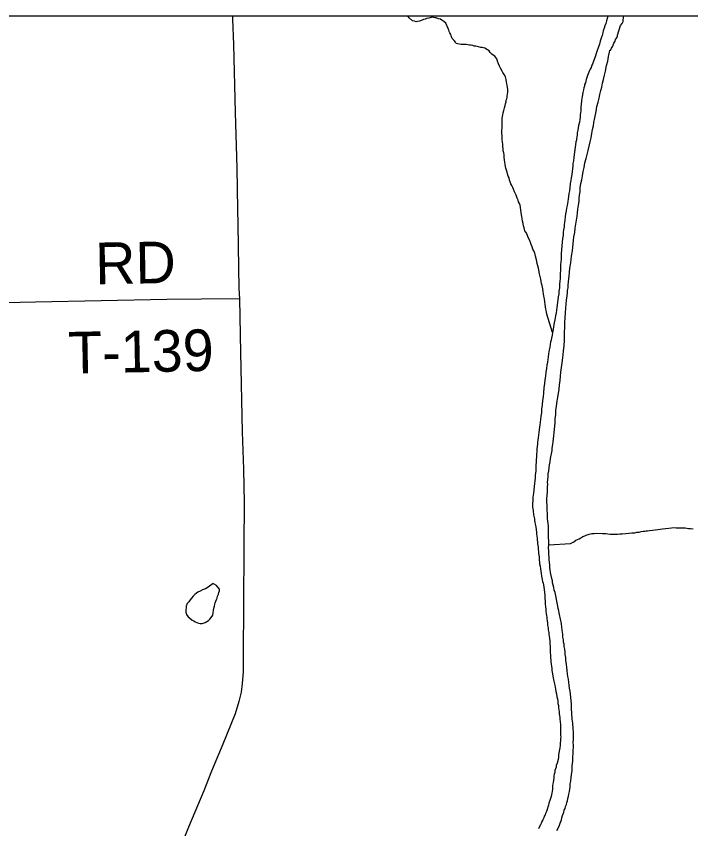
# Model space of a CAD drawing. Extents: x 0 to 34, y 0 to 22.
# Drawn here: x 5.67 to 6.59, y 20.03 to 21.138 of the extents above; entities that cross this region are included whole.
import ezdxf

# ---------------------------------------------------------------- set-up
doc = ezdxf.new("R2010")
doc.units = 0
for name, color, linetype in [('GM_X_County', 7, 'Continuous'), ('GM_X_County_Road', 7, 'Continuous'), ('GM_X_Major_River', 7, 'Continuous'), ('GM_X_Minor_Lake', 7, 'Continuous'), ('GM_X_Minor_River', 7, 'Continuous'), ('GM_X_Township', 7, 'Continuous'), ('GM_X_Township_Road', 7, 'Continuous'), ('GM_X_Township_Road_Text', 7, 'Continuous')]:
    doc.layers.add(name, color=color, linetype=linetype)

msp = doc.modelspace()

# ---------------------------------------------------------------- linework, layer by layer
at = {"layer": 'GM_X_County'}
msp.add_lwpolyline([(9.1622, 14.342), (9.1622, 21.1385), (2.3622, 21.1385), (2.3622, 14.3385), (9.0003, 14.3385)], dxfattribs=at)
at = {"layer": 'GM_X_County_Road'}
msp.add_lwpolyline([(5.965, 21.1385), (5.965, 21.1347), (5.9663, 21.1001), (5.9684, 21.0071), (5.9708, 20.9314), (5.9719, 20.8756), (5.9723, 20.8541), (5.9737, 20.7672), (5.9744, 20.7533), (5.9759, 20.6798), (5.9783, 20.5719), (5.9798, 20.521), (5.9807, 20.4747), (5.9805, 20.4173), (5.98, 20.3324), (5.9795, 20.2706), (5.9795, 20.2444), (5.9783, 20.2284), (5.9766, 20.2165), (5.9737, 20.2042), (5.9686, 20.1872), (5.9517, 20.146), (5.9364, 20.1089), (5.9257, 20.0822), (5.9051, 20.0328), (5.8816, 19.9746)], dxfattribs=at)
at = {"layer": 'GM_X_Major_River'}
for points in [[(6.4766, 21.1385), (6.4758, 21.1355), (6.4747, 21.1321), (6.4737, 21.1287), (6.4726, 21.1252), (6.4715, 21.1222), (6.4705, 21.1187), (6.4698, 21.1157), (6.4687, 21.1122), (6.4676, 21.1084), (6.4662, 21.1046), (6.4652, 21.1004), (6.4634, 21.0954), (6.4623, 21.0916), (6.4609, 21.0877), (6.4598, 21.0843), (6.4566, 21.0759), (6.4559, 21.0732), (6.4544, 21.0709), (6.4537, 21.0686), (6.4526, 21.0663), (6.4515, 21.0643), (6.4508, 21.0621), (6.45, 21.0601), (6.449, 21.0578), (6.4472, 21.0521), (6.4465, 21.0498), (6.4461, 21.0479), (6.445, 21.0452), (6.4447, 21.0433)], [(6.4796, 21.0923), (6.4809, 21.0922), (6.4809, 21.0928), (6.4815, 21.0948), (6.4834, 21.0979), (6.4847, 21.1018), (6.4866, 21.1043), (6.4873, 21.1069), (6.4886, 21.1088), (6.4892, 21.1101), (6.4898, 21.1107), (6.4898, 21.1114), (6.4898, 21.1126), (6.4937, 21.1261), (6.4962, 21.1286), (6.4969, 21.1305), (6.4975, 21.1312), (6.4975, 21.1331), (6.4982, 21.1369), (6.4985, 21.1385)], [(6.4351, 20.8702), (6.4357, 20.8752), (6.4368, 20.8809), (6.4374, 20.8858), (6.4377, 20.8904), (6.438, 20.8946), (6.4387, 20.8992), (6.4389, 20.9045), (6.4399, 20.9102), (6.441, 20.9156), (6.442, 20.9209), (6.443, 20.9266), (6.4444, 20.9324), (6.4454, 20.9388), (6.4472, 20.9446), (6.4486, 20.9499), (6.45, 20.9553), (6.451, 20.9614), (6.4524, 20.9671), (6.4538, 20.9728), (6.4548, 20.9786), (6.4559, 20.9839), (6.4569, 20.9889), (6.4575, 20.9938), (6.4589, 20.9999), (6.4607, 21.0087), (6.4617, 21.0152), (6.4634, 21.0213), (6.4648, 21.0266), (6.4659, 21.032), (6.4669, 21.0373), (6.4683, 21.0419), (6.4693, 21.0473), (6.4708, 21.0522), (6.4722, 21.058), (6.4736, 21.0637), (6.4749, 21.0713), (6.4767, 21.0774), (6.4777, 21.0835), (6.4791, 21.0893), (6.4796, 21.0923)], [(6.4447, 21.0433), (6.444, 21.041), (6.4433, 21.0383), (6.4429, 21.0364), (6.4426, 21.0345), (6.4419, 21.0315), (6.4416, 21.0292), (6.4413, 21.0265), (6.4409, 21.0235), (6.4406, 21.0216), (6.4403, 21.0197), (6.4403, 21.0178), (6.44, 21.0155), (6.44, 21.0136), (6.4397, 21.0117), (6.4397, 21.0094), (6.4394, 21.0067), (6.4391, 21.004), (6.4388, 21.001), (6.4384, 20.9976), (6.4378, 20.9941), (6.4367, 20.9896), (6.4364, 20.9865), (6.4357, 20.9831), (6.435, 20.9796), (6.4347, 20.9766), (6.4344, 20.9735), (6.4341, 20.9716), (6.4337, 20.9694), (6.433, 20.9671), (6.4327, 20.9633), (6.4307, 20.9499), (6.4301, 20.9457), (6.4298, 20.9415), (6.4291, 20.9377), (6.4288, 20.9343), (6.4285, 20.9305), (6.4278, 20.9267), (6.4275, 20.9225), (6.4268, 20.9183), (6.4262, 20.9145), (6.4255, 20.9103), (6.4248, 20.9046), (6.4242, 20.9004), (6.4235, 20.8966), (6.4232, 20.8928), (6.4225, 20.8893), (6.4222, 20.8859), (6.4215, 20.8832), (6.4212, 20.8802), (6.4205, 20.8767), (6.4198, 20.8729), (6.4191, 20.8691), (6.4185, 20.8649), (6.4178, 20.8603), (6.4175, 20.8573), (6.4172, 20.8543), (6.4169, 20.8512), (6.4162, 20.8474), (6.4159, 20.8436), (6.4156, 20.8394), (6.4149, 20.8352), (6.4143, 20.8303), (6.414, 20.8253), (6.4133, 20.8204), (6.4131, 20.8146), (6.4128, 20.8108), (6.4129, 20.8074), (6.4126, 20.8036), (6.4123, 20.7998), (6.4123, 20.796), (6.412, 20.7918), (6.4117, 20.788), (6.4118, 20.7846), (6.4115, 20.7808), (6.4112, 20.7774), (6.4109, 20.7732), (6.4107, 20.7679), (6.41, 20.7637), (6.4097, 20.7599), (6.409, 20.7557), (6.4077, 20.7446), (6.407, 20.7412), (6.4067, 20.7378), (6.4061, 20.7339), (6.4054, 20.7298), (6.4044, 20.7244), (6.4037, 20.7202), (6.4026, 20.7156), (6.402, 20.7114), (6.4013, 20.7072), (6.4006, 20.7034), (6.3999, 20.6996), (6.3992, 20.6969), (6.3985, 20.6943), (6.3982, 20.6908), (6.3975, 20.6874), (6.3965, 20.6836), (6.3958, 20.6783), (6.3952, 20.6741), (6.3949, 20.6703)], [(6.401, 20.3687), (6.4001, 20.3717), (6.3993, 20.3759), (6.3984, 20.3801), (6.398, 20.3835), (6.3975, 20.3869), (6.3974, 20.3903), (6.397, 20.3937), (6.3965, 20.3975), (6.3965, 20.4009), (6.3964, 20.4051), (6.3963, 20.4093), (6.3958, 20.4134), (6.3961, 20.4176), (6.396, 20.4229), (6.3959, 20.4271), (6.3958, 20.4313), (6.3957, 20.4355), (6.3956, 20.4393), (6.3956, 20.4431), (6.3951, 20.4465), (6.395, 20.4499), (6.3946, 20.4537), (6.3945, 20.4571), (6.3944, 20.4605), (6.394, 20.4647), (6.3939, 20.4685), (6.3938, 20.4719), (6.3937, 20.4757), (6.3936, 20.4803), (6.3939, 20.4852), (6.3942, 20.4894), (6.3945, 20.4932), (6.3944, 20.4966), (6.3947, 20.4997), (6.3946, 20.5031), (6.395, 20.5061), (6.3952, 20.5107), (6.3955, 20.5145), (6.3962, 20.5187), (6.3965, 20.5225), (6.3972, 20.5267), (6.3979, 20.5309), (6.3985, 20.5355), (6.4006, 20.5461), (6.4009, 20.5496), (6.4015, 20.5545), (6.4022, 20.5583), (6.4025, 20.5621), (6.4032, 20.5663), (6.4035, 20.5709), (6.4041, 20.5751), (6.4044, 20.5797), (6.4047, 20.5842), (6.405, 20.5895), (6.4056, 20.5953), (6.4059, 20.601), (6.4065, 20.6067), (6.4075, 20.6135), (6.4085, 20.6189), (6.4092, 20.6242), (6.4102, 20.6299), (6.4108, 20.636), (6.4115, 20.6417), (6.4121, 20.6475), (6.4127, 20.6532), (6.4137, 20.6593), (6.4144, 20.6657), (6.4154, 20.6726), (6.4163, 20.6817), (6.4173, 20.6894), (6.4175, 20.6962), (6.4174, 20.7019), (6.4177, 20.7076), (6.4179, 20.7141), (6.4181, 20.7209), (6.4184, 20.7274), (6.419, 20.7338), (6.4196, 20.7403), (6.4199, 20.746), (6.4205, 20.7514), (6.4212, 20.7571), (6.4215, 20.7613), (6.4218, 20.7647), (6.4224, 20.7681), (6.4227, 20.7719), (6.423, 20.7761), (6.4237, 20.7803), (6.424, 20.7845), (6.4243, 20.7891), (6.4249, 20.7951), (6.4263, 20.802), (6.4272, 20.8115), (6.4286, 20.8188), (6.4305, 20.8378), (6.4315, 20.8435), (6.4321, 20.8496), (6.4331, 20.855), (6.4338, 20.8603), (6.4348, 20.8657), (6.4351, 20.8702)], [(6.3949, 20.6703), (6.3942, 20.6668), (6.3935, 20.6626), (6.3928, 20.6581), (6.3922, 20.6531), (6.3915, 20.6478), (6.3909, 20.6428), (6.3902, 20.6375), (6.3896, 20.6318), (6.389, 20.6249), (6.3883, 20.6196), (6.3877, 20.6143), (6.3871, 20.6085), (6.3864, 20.6028), (6.3862, 20.5975), (6.3855, 20.5929), (6.3848, 20.5887), (6.3845, 20.5849), (6.3838, 20.5815), (6.3835, 20.5781), (6.3828, 20.575), (6.3825, 20.5708), (6.3819, 20.5674), (6.3816, 20.5636), (6.3813, 20.5602), (6.3809, 20.5575), (6.3806, 20.5548), (6.3803, 20.5518), (6.38, 20.5487), (6.3797, 20.5449), (6.3794, 20.5415), (6.3789, 20.5297), (6.3785, 20.5267), (6.3786, 20.5236), (6.3783, 20.521), (6.3783, 20.5183), (6.378, 20.5156), (6.3777, 20.5122), (6.3774, 20.5088), (6.3771, 20.505), (6.3768, 20.5012), (6.3761, 20.4974), (6.3759, 20.4924), (6.3752, 20.4882), (6.3749, 20.4852), (6.3745, 20.4825), (6.3742, 20.4791), (6.3743, 20.4772), (6.374, 20.4749), (6.374, 20.4722), (6.3741, 20.4688), (6.3745, 20.4665), (6.3749, 20.4647), (6.375, 20.4624), (6.3754, 20.4605), (6.3754, 20.4586), (6.3759, 20.4567), (6.3763, 20.4548), (6.3767, 20.4529), (6.3767, 20.451), (6.3772, 20.4484), (6.3776, 20.4457), (6.3785, 20.4423), (6.3789, 20.4381), (6.3794, 20.4347), (6.3794, 20.4321), (6.3799, 20.4294), (6.3803, 20.4268), (6.3804, 20.4241), (6.3808, 20.4219), (6.3809, 20.4188), (6.3813, 20.4165), (6.3817, 20.4143), (6.3818, 20.4116), (6.3822, 20.4082), (6.3823, 20.4059), (6.3827, 20.4037), (6.3828, 20.4014), (6.3828, 20.3995), (6.3837, 20.3919), (6.3842, 20.3885), (6.385, 20.3851), (6.3855, 20.3817), (6.3859, 20.3787), (6.3864, 20.3749), (6.3868, 20.3726), (6.3872, 20.3703), (6.3877, 20.3677), (6.3885, 20.3654), (6.3889, 20.3631), (6.3893, 20.3601), (6.3898, 20.3567), (6.3903, 20.3525), (6.3907, 20.3487), (6.3908, 20.3453), (6.3913, 20.3404), (6.3914, 20.3366), (6.3918, 20.3332), (6.3919, 20.3298), (6.392, 20.3267), (6.3924, 20.3241)], [(6.4071, 20.028), (6.4093, 20.0323), (6.4108, 20.0353), (6.4115, 20.038), (6.4126, 20.0403), (6.4133, 20.0426), (6.414, 20.0453), (6.415, 20.0483), (6.4158, 20.0506), (6.4165, 20.0529), (6.4172, 20.0556), (6.4183, 20.0579), (6.419, 20.061), (6.4201, 20.0633), (6.4207, 20.0663), (6.4215, 20.0686), (6.4222, 20.0717), (6.4229, 20.0747), (6.4235, 20.0778), (6.4242, 20.0812), (6.4249, 20.0843), (6.4252, 20.0877), (6.4255, 20.0915), (6.4262, 20.0953), (6.4265, 20.1007), (6.4272, 20.1041), (6.4275, 20.1071), (6.4278, 20.1094), (6.4278, 20.1113), (6.4281, 20.114), (6.428, 20.1163), (6.4284, 20.1193), (6.4287, 20.1227), (6.429, 20.1258), (6.4289, 20.1288), (6.4292, 20.1326), (6.4295, 20.1353), (6.4295, 20.138), (6.4298, 20.141), (6.4297, 20.1444), (6.4296, 20.1482), (6.4299, 20.152), (6.4297, 20.1627), (6.4296, 20.1661), (6.4292, 20.1691), (6.4291, 20.1721), (6.4287, 20.1744), (6.4286, 20.1771), (6.4282, 20.1797), (6.4282, 20.182), (6.4277, 20.1854), (6.4276, 20.1892), (6.4272, 20.193), (6.4271, 20.1968), (6.427, 20.2006), (6.4265, 20.2048), (6.426, 20.2097), (6.4256, 20.2139), (6.4251, 20.218), (6.4246, 20.2222), (6.4238, 20.2264), (6.4233, 20.2301), (6.4229, 20.2343), (6.422, 20.2381), (6.4216, 20.2419), (6.4211, 20.2461), (6.4206, 20.2502), (6.4201, 20.2548), (6.4196, 20.2601), (6.4192, 20.2642), (6.4187, 20.268), (6.4183, 20.2714), (6.4178, 20.2752), (6.4173, 20.279), (6.4169, 20.2821), (6.4164, 20.2851), (6.416, 20.2881), (6.4155, 20.2915), (6.4155, 20.2957), (6.4146, 20.3014), (6.4141, 20.3056), (6.4133, 20.3093), (6.4128, 20.3127), (6.412, 20.3161), (6.4115, 20.3184), (6.4111, 20.3203), (6.4107, 20.3226), (6.4103, 20.3248), (6.4098, 20.3275), (6.409, 20.3309), (6.4085, 20.3339), (6.4077, 20.3385), (6.4056, 20.3483), (6.4047, 20.3525), (6.4035, 20.3559), (6.4031, 20.3596), (6.4022, 20.3627), (6.4014, 20.3657), (6.401, 20.3687)], [(6.3924, 20.3241), (6.3928, 20.321), (6.3933, 20.3188), (6.3937, 20.3165), (6.3941, 20.3139), (6.3942, 20.3108), (6.3946, 20.3082), (6.3951, 20.3044), (6.3955, 20.3017), (6.396, 20.2979), (6.3961, 20.2957), (6.3965, 20.293), (6.3969, 20.29), (6.3974, 20.2866), (6.3975, 20.2832), (6.3979, 20.279), (6.398, 20.2748), (6.3981, 20.2703), (6.3986, 20.2676), (6.3986, 20.2653), (6.3987, 20.263), (6.3991, 20.2608), (6.3991, 20.2581), (6.3996, 20.2551), (6.4, 20.2521), (6.4001, 20.249), (6.4002, 20.2464), (6.4006, 20.2441), (6.4023, 20.2361), (6.4027, 20.2339), (6.4031, 20.2316), (6.404, 20.2282), (6.4044, 20.2263), (6.4048, 20.2237), (6.4053, 20.2206), (6.4057, 20.2176), (6.4065, 20.2146), (6.407, 20.2104), (6.4078, 20.2074), (6.4083, 20.2044), (6.4087, 20.2013), (6.4092, 20.1983), (6.4092, 20.1953), (6.4097, 20.1926), (6.4101, 20.19), (6.4102, 20.1873), (6.4106, 20.1847), (6.411, 20.182), (6.4111, 20.1797), (6.4115, 20.1763), (6.412, 20.1725), (6.4121, 20.1702), (6.4121, 20.1683), (6.4121, 20.1665), (6.4122, 20.1642), (6.4122, 20.1615), (6.4123, 20.1596), (6.4123, 20.1577), (6.4124, 20.1558), (6.412, 20.1532), (6.4121, 20.1509), (6.4118, 20.1471), (6.4115, 20.1444), (6.4112, 20.141), (6.4108, 20.1383), (6.4105, 20.1364), (6.4098, 20.1341), (6.4095, 20.1307), (6.4092, 20.128), (6.4088, 20.125), (6.4074, 20.12), (6.4064, 20.1166), (6.406, 20.1146), (6.4053, 20.112), (6.4046, 20.1097), (6.4043, 20.107), (6.4036, 20.1047), (6.4032, 20.102), (6.4029, 20.0998), (6.4026, 20.0967), (6.4019, 20.0937), (6.4016, 20.0918), (6.4012, 20.0891), (6.401, 20.0845), (6.4006, 20.0815), (6.4003, 20.0788), (6.4, 20.0769), (6.3993, 20.0746), (6.3986, 20.0719), (6.3975, 20.0689), (6.3964, 20.0654), (6.3957, 20.0627), (6.395, 20.0601), (6.3943, 20.0582), (6.3929, 20.0539), (6.3918, 20.0513), (6.3911, 20.0493), (6.39, 20.0474), (6.3892, 20.0451), (6.3882, 20.0428), (6.3867, 20.0401)], [(6.3867, 20.0401), (6.3856, 20.0378), (6.3849, 20.0359), (6.383, 20.0325), (6.382, 20.0302)]]:
    msp.add_lwpolyline(points, dxfattribs=at)
at = {"layer": 'GM_X_Minor_Lake'}
for points in [[(5.9385, 20.3648), (5.9317, 20.3597), (5.928, 20.3577), (5.9238, 20.3561), (5.9208, 20.3545), (5.9178, 20.3533), (5.9159, 20.3517), (5.9137, 20.3498), (5.9114, 20.3474), (5.9092, 20.3447), (5.9074, 20.3428), (5.9055, 20.3401), (5.9033, 20.3374), (5.9018, 20.3339), (5.9015, 20.3313), (5.9012, 20.3294), (5.9012, 20.3275), (5.9013, 20.3256), (5.9021, 20.3225), (5.9044, 20.3196), (5.9064, 20.3181), (5.9099, 20.3151), (5.9122, 20.314), (5.9141, 20.3125), (5.9164, 20.3115), (5.9187, 20.3108)], [(5.9385, 20.3648), (5.9317, 20.3597), (5.928, 20.3577), (5.9238, 20.3561), (5.9208, 20.3545), (5.9178, 20.3533), (5.9159, 20.3517), (5.9137, 20.3498), (5.9114, 20.3474), (5.9092, 20.3447), (5.9074, 20.3428), (5.9055, 20.3401), (5.9033, 20.3374), (5.9018, 20.3339), (5.9015, 20.3313), (5.9012, 20.3294), (5.9012, 20.3275), (5.9013, 20.3256), (5.9021, 20.3225), (5.9044, 20.3196), (5.9064, 20.3181), (5.9099, 20.3151), (5.9122, 20.314), (5.9141, 20.3125), (5.9164, 20.3115), (5.9187, 20.3108), (5.921, 20.3104), (5.9236, 20.3105), (5.9278, 20.3117), (5.9297, 20.3129), (5.9323, 20.3145), (5.9338, 20.3164), (5.936, 20.3187), (5.9379, 20.3218), (5.9385, 20.3252), (5.9389, 20.3279), (5.9396, 20.3313), (5.9403, 20.334), (5.941, 20.3367), (5.9413, 20.3386), (5.942, 20.3409), (5.9431, 20.3432), (5.9438, 20.3451), (5.9445, 20.3474), (5.9456, 20.3505), (5.9463, 20.3524), (5.947, 20.3551), (5.947, 20.3573), (5.9431, 20.3622), (5.94, 20.364), (5.9389, 20.3644), (5.9385, 20.3648)], [(5.9187, 20.3108), (5.921, 20.3104), (5.9236, 20.3105), (5.9278, 20.3117), (5.9297, 20.3129), (5.9323, 20.3145), (5.9338, 20.3164), (5.936, 20.3187), (5.9379, 20.3218), (5.9385, 20.3252), (5.9389, 20.3279), (5.9396, 20.3313), (5.9403, 20.334), (5.941, 20.3367), (5.9413, 20.3386), (5.942, 20.3409), (5.9431, 20.3432), (5.9438, 20.3451), (5.9445, 20.3474), (5.9456, 20.3505), (5.9463, 20.3524), (5.947, 20.3551), (5.947, 20.3573), (5.9431, 20.3622), (5.94, 20.364), (5.9389, 20.3644), (5.9385, 20.3648)]]:
    msp.add_lwpolyline(points, dxfattribs=at)
at = {"layer": 'GM_X_Minor_River'}
for points in [[(6.3399, 21.0323), (6.3403, 21.035), (6.3402, 21.0372), (6.3402, 21.0391), (6.3397, 21.0414), (6.3393, 21.0444), (6.3389, 21.0463), (6.3384, 21.049), (6.338, 21.0524), (6.3372, 21.0558), (6.3352, 21.0592), (6.3336, 21.0618), (6.3328, 21.0637), (6.3301, 21.0678), (6.3289, 21.0704), (6.3276, 21.0734), (6.3264, 21.0772), (6.3252, 21.0802), (6.324, 21.0821), (6.3225, 21.084), (6.3205, 21.0854), (6.3186, 21.0869), (6.3163, 21.0892), (6.3147, 21.0914), (6.3124, 21.0929), (6.3089, 21.0951), (6.3055, 21.0958), (6.3036, 21.0961), (6.3005, 21.0968), (6.2986, 21.0971), (6.2967, 21.0975), (6.2944, 21.0978), (6.2925, 21.0985), (6.2902, 21.0989), (6.2879, 21.0992), (6.2856, 21.0995), (6.2833, 21.0998), (6.2814, 21.0998), (6.2795, 21.0998), (6.2765, 21.1001), (6.2742, 21.1004), (6.2719, 21.1011), (6.27, 21.1014), (6.2688, 21.1033), (6.2672, 21.1056), (6.2645, 21.1082), (6.2629, 21.1116), (6.2625, 21.1138), (6.2613, 21.1157), (6.2605, 21.1176), (6.2597, 21.1195), (6.2589, 21.1217), (6.2557, 21.1289), (6.253, 21.1315), (6.2503, 21.1333), (6.2484, 21.1344), (6.2457, 21.1351), (6.2426, 21.1362), (6.2407, 21.1365), (6.2373, 21.1372), (6.2327, 21.136), (6.2293, 21.1355), (6.2274, 21.1347), (6.2255, 21.1339), (6.2233, 21.1331), (6.2199, 21.1319), (6.2172, 21.1315), (6.2153, 21.131), (6.213, 21.1318), (6.2104, 21.1321), (6.2057, 21.1362), (6.2042, 21.138), (6.2039, 21.1385)], [(6.4013, 20.7072), (6.3935, 20.7322), (6.3931, 20.7356), (6.3923, 20.739), (6.3918, 20.742), (6.3914, 20.7454), (6.3909, 20.7488), (6.3904, 20.753), (6.3896, 20.7568), (6.3891, 20.7598), (6.3883, 20.7628), (6.3879, 20.7666), (6.387, 20.7711), (6.3862, 20.7742), (6.3857, 20.7768), (6.3853, 20.7799), (6.3845, 20.7836), (6.3836, 20.787), (6.3819, 20.795), (6.3811, 20.798), (6.3803, 20.8014), (6.3794, 20.8063), (6.3782, 20.8112), (6.3769, 20.8154), (6.3757, 20.8188), (6.3745, 20.821), (6.3737, 20.8241), (6.3721, 20.8274), (6.3713, 20.8301), (6.3697, 20.8338), (6.3681, 20.8368), (6.3665, 20.841), (6.3649, 20.844), (6.3637, 20.8459), (6.3629, 20.8478), (6.3625, 20.85), (6.3617, 20.8527), (6.3612, 20.8557), (6.3604, 20.8591), (6.3599, 20.8625), (6.3595, 20.8652), (6.3591, 20.8678), (6.3586, 20.8708), (6.3582, 20.8742), (6.3577, 20.8777), (6.3569, 20.8807), (6.3561, 20.8829), (6.3549, 20.8852), (6.3545, 20.8875), (6.3532, 20.8905), (6.3516, 20.8946), (6.3496, 20.8991), (6.348, 20.9029), (6.3465, 20.9059), (6.3457, 20.9078), (6.3445, 20.91), (6.3436, 20.9127), (6.3428, 20.915), (6.342, 20.918), (6.3408, 20.9206), (6.34, 20.9236), (6.3392, 20.9259), (6.3384, 20.9285), (6.3375, 20.9312), (6.3371, 20.9338), (6.3358, 20.9425), (6.3353, 20.9459), (6.3352, 20.9494), (6.3348, 20.9524), (6.334, 20.955), (6.3339, 20.9573), (6.3335, 20.9611), (6.3334, 20.9638), (6.333, 20.9672), (6.3325, 20.9698), (6.3325, 20.9729), (6.3324, 20.9759), (6.3323, 20.9789), (6.3323, 20.9827), (6.3326, 20.9865), (6.3325, 20.9903), (6.3324, 20.9938), (6.3327, 20.9964), (6.3327, 20.9987), (6.333, 21.0017), (6.3337, 21.004), (6.334, 21.0067), (6.3347, 21.0098), (6.3358, 21.0136), (6.3365, 21.0166), (6.3372, 21.0189), (6.3379, 21.0216), (6.3382, 21.0239), (6.3389, 21.0258), (6.3393, 21.0277), (6.3396, 21.0296), (6.3399, 21.0323)], [(6.3961, 20.4176), (6.4257, 20.4194), (6.4276, 20.4202), (6.4302, 20.4218), (6.4332, 20.4238), (6.4374, 20.4257), (6.44, 20.4273), (6.4426, 20.4289), (6.4453, 20.4301), (6.4472, 20.4309), (6.4513, 20.4321), (6.4547, 20.433), (6.4582, 20.433), (6.4616, 20.4335), (6.4696, 20.4333), (6.4718, 20.4333), (6.4741, 20.433), (6.4768, 20.4327), (6.4799, 20.4324), (6.4825, 20.4324), (6.4848, 20.4321), (6.4871, 20.4321), (6.4897, 20.4322), (6.4928, 20.4326), (6.4962, 20.4327), (6.5011, 20.4332), (6.5053, 20.4337), (6.5095, 20.4338), (6.5133, 20.4342), (6.5163, 20.4347), (6.5194, 20.4351), (6.522, 20.4359), (6.5247, 20.4364), (6.5269, 20.4364), (6.5288, 20.4368), (6.5307, 20.4369), (6.5334, 20.4373), (6.5376, 20.4378), (6.541, 20.4382), (6.5448, 20.4387), (6.5482, 20.4392), (6.5512, 20.4396), (6.5554, 20.4401), (6.5596, 20.4405), (6.5634, 20.441), (6.5668, 20.4411), (6.5698, 20.4408), (6.5729, 20.4408), (6.5771, 20.4409), (6.5797, 20.4406), (6.582, 20.4407), (6.5843, 20.4403), (6.5866, 20.44), (6.5893, 20.4397), (6.5931, 20.4394)]]:
    msp.add_lwpolyline(points, dxfattribs=at)
at = {"layer": 'GM_X_Township'}
msp.add_line((9.1291, 21.1385), (4.3953, 21.1385), dxfattribs=at)
at = {"layer": 'GM_X_Township_Road'}
msp.add_lwpolyline([(5.9744, 20.7533), (5.9226, 20.7525), (5.8755, 20.7523), (5.6964, 20.7487), (5.6326, 20.747)], dxfattribs=at)

# ---------------------------------------------------------------- texts
at = {"layer": 'GM_X_Township_Road_Text'}
for s, rotation, p in [('RD', 0.9891, (5.7782, 20.7729)), ('T-139', 1.1237, (5.7413, 20.6511))]:
    msp.add_text(s, height=0.05682, rotation=rotation, dxfattribs=at).set_placement(p)

doc.saveas('drawing.dxf')
